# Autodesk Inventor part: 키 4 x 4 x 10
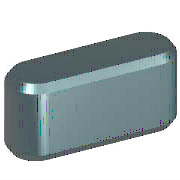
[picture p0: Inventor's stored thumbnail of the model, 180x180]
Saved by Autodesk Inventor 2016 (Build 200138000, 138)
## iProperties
IsCustomPart: 1
Created: 2012-02
Part Number: 키 4 x 4 x 10
Material: 강철, 연강
Description: 키 및 해당 키홈
Document SubType Name: Modeling
Standard: KS B 1311
Designer: test
Standards Organization: KS
Language: ko-KR
Size Designation: 4 x 4 x 10
Categories: <MemberInstance><Categories><Category DisplayName="샤프트 부품" InternalName="7f7aeb1f-a693-4053-b835-cee3144e0d98" Mnemonic="SHFT"><Category DisplayName="키" Interna
Density: 1 g/cm^3
Appearance: 노란색
Author: test
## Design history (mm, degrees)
workplane "Work Plane1"
workplane "Work Plane2"
sketch "스케치1"
  geometry: L1 (2, 2)-(8, 2); L2 (8, -2)-(2, -2); L3 (0, 9.4)-(0, -7.4) reference; L4 (-5, 0)-(30, 0) reference; L5 (10, 0)-(10, 7); A1 r 2 centre (2, 0) between (2, 2) and (2, -2); A2 r 2 centre (8, 0) between (8, -2) and (8, 2)
  constraints: 6 end point, 5 point on circle, 4 tangent, 3 point on line, 2 centre point, 1 horizontal, 1 parallel, 1 perpendicular
  dimensions: "d0" = 2 radius of A1 (= 0.5 x PB); "d13" = 2 radius of A2 (= 0.5 x PB); "d14" = 10 distance between parallel lines of L5 L3 (= NLG)
extrude "본체1" new body sketch "스케치1" taper "d3" = 0 deg; stored distance "d4" = 10
workplane "Work Plane3"
body "Solid1"
chamfer "모따기1" distance "d8" = 0.25 (= PHH); stored, may be unused: second distance "d9" = 0.25 (= PHH), angle "d15" = 45 deg
other parameters: "d1" = -2.5 (= -PNT), "d2" = 1.5 (= PH - PNT), "NLG" = 10 [user parameter; used in 3 equation terms], "PB" = 4 [user parameter; used in 2 equation terms], "PNT" = 2.5 [user parameter; used in 2 equation terms], "PH" = 4 [user parameter; used in 1 equation term], "PHH" = 0.25 [user parameter; used in 2 equation terms], "d10" = 0, "d16" = 0, "d17" = 0, "d18" = 0, "WDMAX" = 12 [user parameter], "RR" = 0.08 [user parameter], "PUEB" = 1.8 [user parameter]
